Omron CX-Programmer project NuevoProyecto (CX-Programmer 9.50)

# PLC NewPLC1: CP1L-E EM

## Program P6_1_GRAFCET3 (cyclic task 0)
Local symbols
Etapa_0 10.00 BOOL
Etapa_1 10.01 BOOL
Etapa_10 10.10 BOOL
Etapa_11 10.11 BOOL
Etapa_12 10.12 BOOL
Etapa_2 10.02 BOOL
Etapa_3 10.03 BOOL
Etapa_4 10.04 BOOL
Etapa_5 10.05 BOOL
Etapa_6 10.06 BOOL
Etapa_7 10.07 BOOL
Etapa_8 10.08 BOOL
Etapa_9 10.09 BOOL
F1 0.04 BOOL
F2 0.05 BOOL
FAP 0.06 BOOL
FB 0.03 BOOL
FCP 0.07 BOOL
Fot 0.08 BOOL
KAP 100.02 BOOL
KB 100.01 BOOL
KCP 100.03 BOOL
KS 100.00 BOOL
P1 0.01 BOOL
P2 0.02 BOOL
PB 0.00 BOOL

### Section Sección1_Programa_principal
; Programa principal (Etapas 0 ... 12)

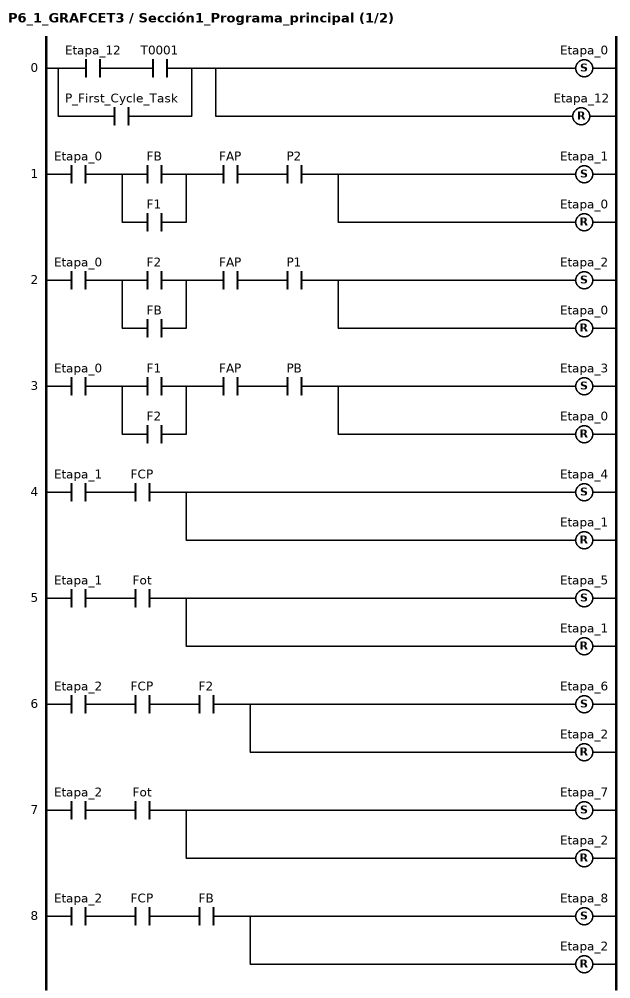
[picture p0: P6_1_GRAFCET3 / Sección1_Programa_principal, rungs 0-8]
; rung 0
LD Etapa_12
AND T0001
OR P_First_Cycle_Task
SET Etapa_0
RSET Etapa_12
; rung 1
LD Etapa_0
LD FB
OR F1
ANDLD
AND FAP
AND P2
SET Etapa_1
RSET Etapa_0
; rung 2
LD Etapa_0
LD F2
OR FB
ANDLD
AND FAP
AND P1
SET Etapa_2
RSET Etapa_0
; rung 3
LD Etapa_0
LD F1
OR F2
ANDLD
AND FAP
AND PB
SET Etapa_3
RSET Etapa_0
; rung 4
LD Etapa_1
AND FCP
SET Etapa_4
RSET Etapa_1
; rung 5
LD Etapa_1
AND Fot
SET Etapa_5
RSET Etapa_1
; rung 6
LD Etapa_2
AND FCP
AND F2
SET Etapa_6
RSET Etapa_2
; rung 7
LD Etapa_2
AND Fot
SET Etapa_7
RSET Etapa_2
; rung 8
LD Etapa_2
AND FCP
AND FB
SET Etapa_8
RSET Etapa_2

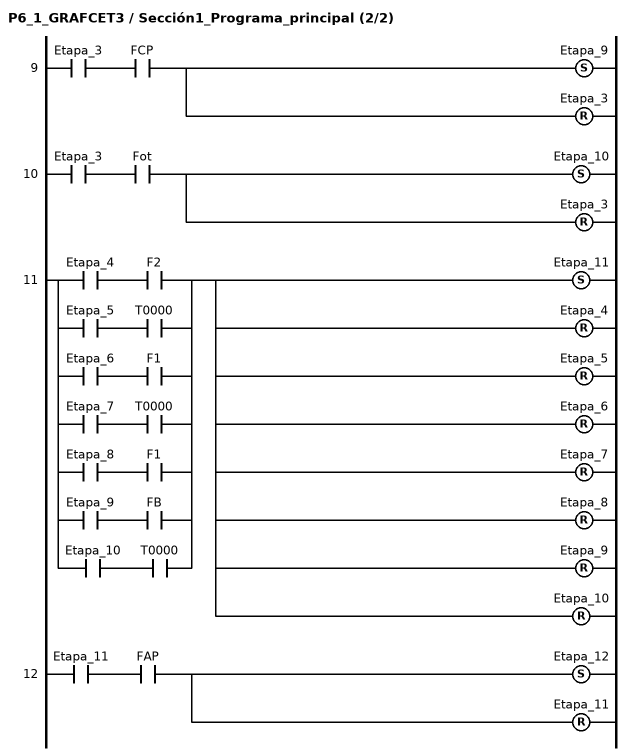
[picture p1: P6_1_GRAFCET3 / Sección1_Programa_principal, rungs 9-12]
; rung 9
LD Etapa_3
AND FCP
SET Etapa_9
RSET Etapa_3
; rung 10
LD Etapa_3
AND Fot
SET Etapa_10
RSET Etapa_3
; rung 11
LD Etapa_4
AND F2
LD Etapa_5
AND T0000
ORLD
LD Etapa_6
AND F1
ORLD
LD Etapa_7
AND T0000
ORLD
LD Etapa_8
AND F1
ORLD
LD Etapa_9
AND FB
ORLD
LD Etapa_10
AND T0000
ORLD
SET Etapa_11
RSET Etapa_4
RSET Etapa_5
RSET Etapa_6
RSET Etapa_7
RSET Etapa_8
RSET Etapa_9
RSET Etapa_10
; rung 12
LD Etapa_11
AND FAP
SET Etapa_12
RSET Etapa_11

### Section Sección2_Temporizadores

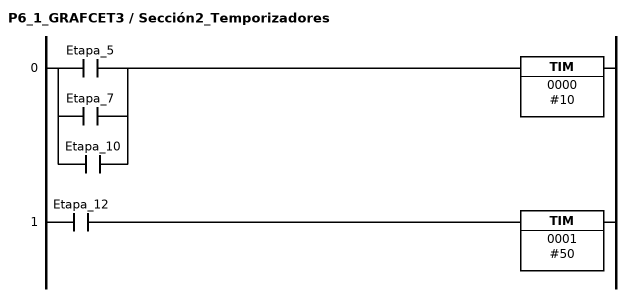
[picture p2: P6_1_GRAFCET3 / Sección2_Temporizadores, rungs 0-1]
; rung 0
LD Etapa_5
OR Etapa_7
OR Etapa_10
TIM 0000 #10
; rung 1
LD Etapa_12
TIM 0001 #50

### Section Sección3_Salidas

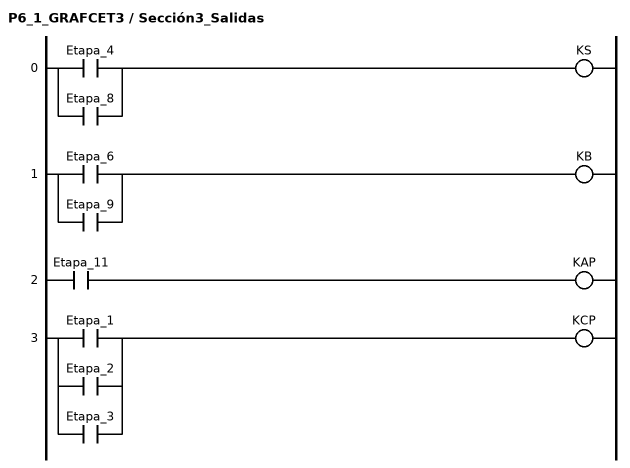
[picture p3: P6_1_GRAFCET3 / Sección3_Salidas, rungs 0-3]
; rung 0
LD Etapa_4
OR Etapa_8
OUT KS
; rung 1
LD Etapa_6
OR Etapa_9
OUT KB
; rung 2
LD Etapa_11
OUT KAP
; rung 3
LD Etapa_1
OR Etapa_2
OR Etapa_3
OUT KCP

### Section Sección4_END
; rung 0: Fin de programa
END(001)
